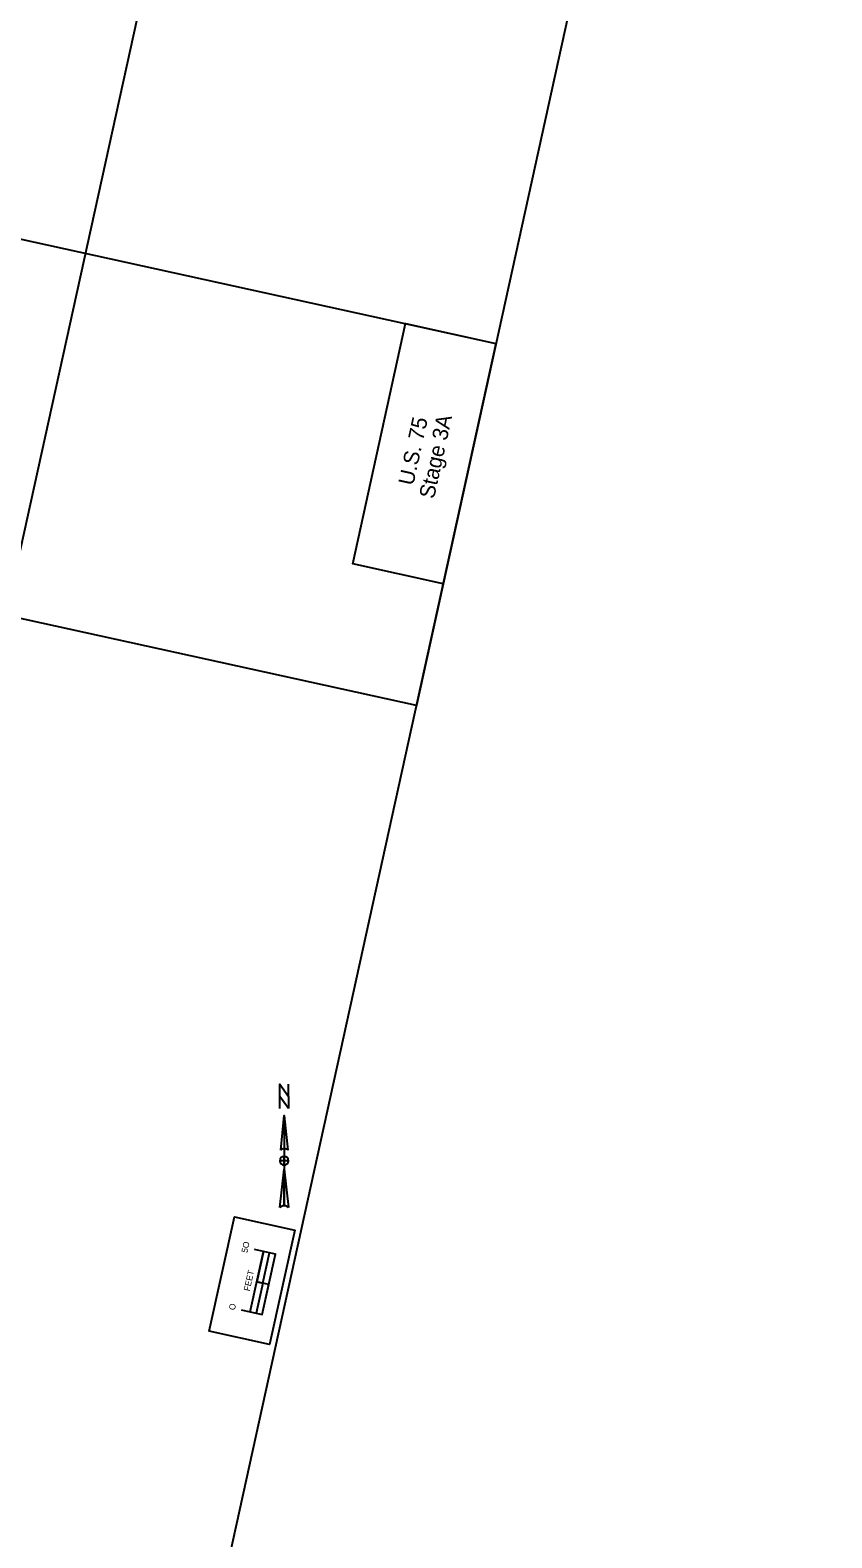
# Model space of a CAD drawing. Extents: x 14104283 to 14129344, y 8637090 to 8673339.
# Drawn here: x 14108164 to 14108813, y 8638989 to 8640210 of the extents above; entities that cross this region are included whole.
import ezdxf

# ---------------------------------------------------------------- set-up
doc = ezdxf.new("R2010")
doc.units = 0
for name, color, linetype in [('dsnCellsNorthArrow', 7, 'Continuous'), ('dsnCellsScaleBlock', 7, 'Continuous'), ('dsnNonPlotable', 7, 'Continuous'), ('dsnTextOverlapEven', 7, 'Continuous')]:
    doc.layers.add(name, color=color, linetype=linetype)

msp = doc.modelspace()

# ---------------------------------------------------------------- linework, layer by layer
at = {"layer": 'dsnCellsNorthArrow'}
for p, q in [((14108369.8, 8639331.3), (14108372.7, 8639303.2)), ((14108369.8, 8639331.3), (14108369.8, 8639258.1)), ((14108367, 8639303.2), (14108367, 8639303.2)), ((14108367.1, 8639303.4), (14108367.7, 8639304)), ((14108366.3, 8639256.7), (14108369.8, 8639287.7)), ((14108369.8, 8639291.2), (14108369.8, 8639291.2))]:
    msp.add_line(p, q, dxfattribs=at)
msp.add_lwpolyline([(14108373.4, 8639337), (14108366.3, 8639346.8), (14108366.3, 8639356.7), (14108373.4, 8639346.8)], close=True, dxfattribs=at)
for points in [[(14108366.3, 8639337), (14108366.3, 8639356.7), (14108373.4, 8639346.8), (14108373.4, 8639356.7)], [(14108367, 8639303.2), (14108369.8, 8639331.3), (14108369.8, 8639304.6)], [(14108369.8, 8639291.2), (14108369.8, 8639294.7), (14108366.3, 8639294.7)], [(14108373.4, 8639294.7), (14108369.8, 8639294.7), (14108369.8, 8639298.2)], [(14108369.8, 8639258.1), (14108369.8, 8639287.7), (14108373.4, 8639256.7)]]:
    msp.add_lwpolyline(points, dxfattribs=at)
for centre, radius, start, end in [((14108369.8, 8639294.7), 3.52, 90, 180), ((14108369.8, 8639294.7), 3.52, 180, 270), ((14108369.9, 8639301), 3.52, 90.0204, 143.1257), ((14108369.9, 8639301), 3.52, 36.8481, 90.0218), ((14108369.8, 8639294.7), 3.52, 0, 90), ((14108369.8, 8639294.7), 3.52, 270, 360), ((14108369.8, 8639253), 5.1, 89.9894, 133.619), ((14108369.8, 8639253), 5.11, 46.4021, 90.0006)]:
    msp.add_arc(centre, radius, start, end, dxfattribs=at)
at = {"layer": 'dsnCellsScaleBlock'}
msp.add_line((14108357.5, 8639194.5), (14108347.7, 8639196.6), dxfattribs=at)
msp.add_line((14108357.5, 8639194.5), (14108347.7, 8639196.6), dxfattribs=at)
for points in [[(14108358, 8639145.7), (14108309.2, 8639156.5), (14108329.6, 8639249.3), (14108378.4, 8639238.5)], [(14108309.2, 8639156.5), (14108329.6, 8639249.3), (14108378.4, 8639238.5), (14108358, 8639145.7)], [(14108358, 8639145.7), (14108309.2, 8639156.5), (14108329.6, 8639249.3), (14108378.4, 8639238.5)], [(14108352.6, 8639195.6), (14108357.9, 8639220), (14108353.1, 8639221.1), (14108347.7, 8639196.6)], [(14108352.1, 8639170.1), (14108357.5, 8639194.5), (14108352.6, 8639195.6), (14108347.2, 8639171.2)]]:
    msp.add_lwpolyline(points, close=True, dxfattribs=at)
for points in [[(14108335, 8639173.8), (14108352.1, 8639170.1), (14108362.8, 8639218.9), (14108345.8, 8639222.7)], [(14108342.3, 8639172.2), (14108353.1, 8639221.1)]]:
    msp.add_lwpolyline(points, dxfattribs=at)
at = {"layer": 'dsnNonPlotable'}
for points in [[(14107490.5, 8639880.3), (14107826.8, 8641411.3), (14108813.3, 8641194.5), (14108476.9, 8639663.5)], [(14107651.3, 8639844.9), (14107987.7, 8641375.9), (14108480.9, 8641267.5), (14108144.5, 8639736.6)], [(14107218.4, 8638642.3), (14107554.8, 8640173.3), (14108541.3, 8639956.6), (14108204.9, 8638425.6)]]:
    msp.add_lwpolyline(points, close=True, dxfattribs=at)
at = {"layer": 'dsnTextOverlapEven'}
for points in [[(14108541.3, 8639956.6), (14108498.5, 8639761.9), (14108425.3, 8639778), (14108468, 8639972.7)], [(14108425.3, 8639778), (14108468, 8639972.7), (14108541.3, 8639956.6), (14108498.5, 8639761.9)]]:
    msp.add_lwpolyline(points, close=True, dxfattribs=at)

# ---------------------------------------------------------------- texts
at = {"layer": 'dsnCellsScaleBlock'}
for s, p in [('5O', (14108340, 8639219.8)), ('FEET', (14108341.9, 8639188.7)), ('O', (14108329.8, 8639173.3))]:
    msp.add_text(s, height=5, rotation=77.6078, dxfattribs=at).set_placement(p)
at = {"layer": 'dsnTextOverlapEven'}
for s, p in [('U.S. 75', (14108474.3, 8639841)), ('Stage 3A', (14108491.1, 8639830.2))]:
    msp.add_text(s, height=12.5, rotation=77.6078, dxfattribs=at).set_placement(p)

doc.saveas('drawing.dxf')
